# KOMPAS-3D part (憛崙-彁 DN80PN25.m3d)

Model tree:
1. Объединить компоненты:1  (labels: СЕНС-ПР DN80PN25)

Referenced files in D:\Савин\!СЕНСОР\3D для заказчика\!Новый перечень\СЕНС-ПР\1. СЕНС-ПР\DN80\: СЕНС-ПР DN80PN25.a3d
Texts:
  СЕНС-ПР DN80PN25
  ООО НПП Сенсор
